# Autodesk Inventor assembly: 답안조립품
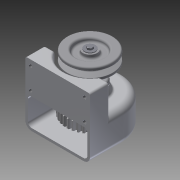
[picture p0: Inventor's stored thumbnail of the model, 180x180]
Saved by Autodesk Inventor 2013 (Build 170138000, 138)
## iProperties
Created: 2015-02
Part Number: 답안조립품
Document SubType Name: Assembly
Designer: Administrator
Author: Administrator
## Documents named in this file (14)
- C:\Documents and Settings\Administrator\바탕 화면\450214V1012\답안조립품.iam
- C:\Documents and Settings\Administrator\바탕 화면\450214V1012\1-본체.ipt
- C:\Documents and Settings\Administrator\바탕 화면\450214V1012\베어링 6001.ipt
- C:\Documents and Settings\Administrator\바탕 화면\450214V1012\키5x5.ipt
- C:\Documents and Settings\Administrator\바탕 화면\450214V1012\축.ipt
- C:\Documents and Settings\Administrator\바탕 화면\450214V1012\5-스퍼기어.ipt
- C:\Documents and Settings\Administrator\바탕 화면\450214V1012\축커버.ipt
- C:\Documents and Settings\Administrator\바탕 화면\450214V1012\오일실.ipt
- C:\Documents and Settings\Administrator\바탕 화면\450214V1012\M3x0.5.ipt
- C:\Documents and Settings\Administrator\바탕 화면\450214V1012\키4x4.ipt
- C:\Documents and Settings\Administrator\바탕 화면\450214V1012\4-V-벨트풀리.ipt
- C:\Documents and Settings\Administrator\바탕 화면\450214V1012\M5x0.8.ipt
- M5x0.8.ipt
- C:\Documents and Settings\Administrator\바탕 화면\450214V1012\와샤.ipt
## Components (7 placed, 4 different names)
1. 1-본체:1
2. 4-V-벨트풀리:1 — 플러쉬:1, 각도:4
3. M5x0.8:1
4. M3x0.5:1
5. M3x0.5:2
6. M3x0.5:3
7. M3x0.5:4
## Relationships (2: Flush 1, Angle 1)
- 플러쉬:1 [Flush]: 4-V-벨트풀리:1
- 각도:4 [Angle]: 4-V-벨트풀리:1
